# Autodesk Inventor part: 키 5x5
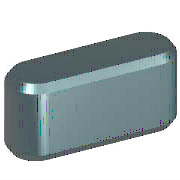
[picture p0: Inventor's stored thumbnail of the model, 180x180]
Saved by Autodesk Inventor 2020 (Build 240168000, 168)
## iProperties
Created: 2012-02
Part Number: 키 5x5
Material: 강철, 연강
Description: 키 및 해당 키홈
Document SubType Name: Modeling
Standard: KS B 1311
Designer: mduedu
Standards Organization: KS
Language: ko-KR
Size Designation: 5 x 5 x 16
Categories: <MemberInstance><Categories><Category DisplayName="샤프트 부품" InternalName="7f7aeb1f-a693-4053-b835-cee3144e0d98" Mnemonic="SHFT"><Category DisplayName="키" Interna
Density: 1 g/cm^3
Appearance: 노란색
IsCustomPart: 1
Author: mduedu
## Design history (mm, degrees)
workplane "Work Plane1"
workplane "Work Plane2"
sketch "스케치1"
  geometry: L1 (2.5, 2.5)-(13.5, 2.5); L2 (13.5, -2.5)-(2.5, -2.5); L3 (0, 9.4)-(0, -7.4) reference; L4 (-5, 0)-(30, 0) reference; L5 (16, 0)-(16, 7); A1 r 2.5 centre (2.5, 0) between (2.5, 2.5) and (2.5, -2.5); A2 r 2.5 centre (13.5, 0) between (13.5, -2.5) and (13.5, 2.5)
  constraints: 6 end point, 5 point on circle, 4 tangent, 3 point on line, 2 centre point, 1 horizontal, 1 parallel, 1 perpendicular
  dimensions: "d0" = 2.5 radius of A1 (= 0.5 x PB); "d13" = 2.5 radius of A2 (= 0.5 x PB); "d14" = 16 distance between parallel lines of L5 L3 (= NLG)
extrude "본체1" new body sketch "스케치1" taper "d3" = 0 deg; stored distance "d4" = 10
workplane "Work Plane3"
body "Solid1"
chamfer "모따기1" distance "d8" = 0.4 (= PHH); stored, may be unused: second distance "d9" = 0.4 (= PHH), angle "d15" = 45 deg
other parameters: "d1" = -3 (= -PNT), "d2" = 2 (= PH - PNT), "NLG" = 16 [user parameter; used in 3 equation terms], "PB" = 5 [user parameter; used in 2 equation terms], "PNT" = 3 [user parameter; used in 2 equation terms], "PH" = 5 [user parameter; used in 1 equation term], "PHH" = 0.4 [user parameter; used in 2 equation terms], "d10" = 0, "d16" = 0, "d17" = 0, "d18" = 0, "WDMIN" = 12 [user parameter], "PLB2" = 16 (= NLG) [user parameter], "WDMAX" = 17 [user parameter], "PLB1" = 16 (= NLG) [user parameter], "RR" = 0.16 [user parameter], "PUEB" = 2.3 [user parameter]
